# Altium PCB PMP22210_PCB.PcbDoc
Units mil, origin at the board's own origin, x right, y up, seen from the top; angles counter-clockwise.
Board outline 1350 x 1350 mil, 2 copper layers (Top Layer, Bottom Layer), stack 62 mil thick; 26 components, 12 nets, 50 pads, 14 vias.
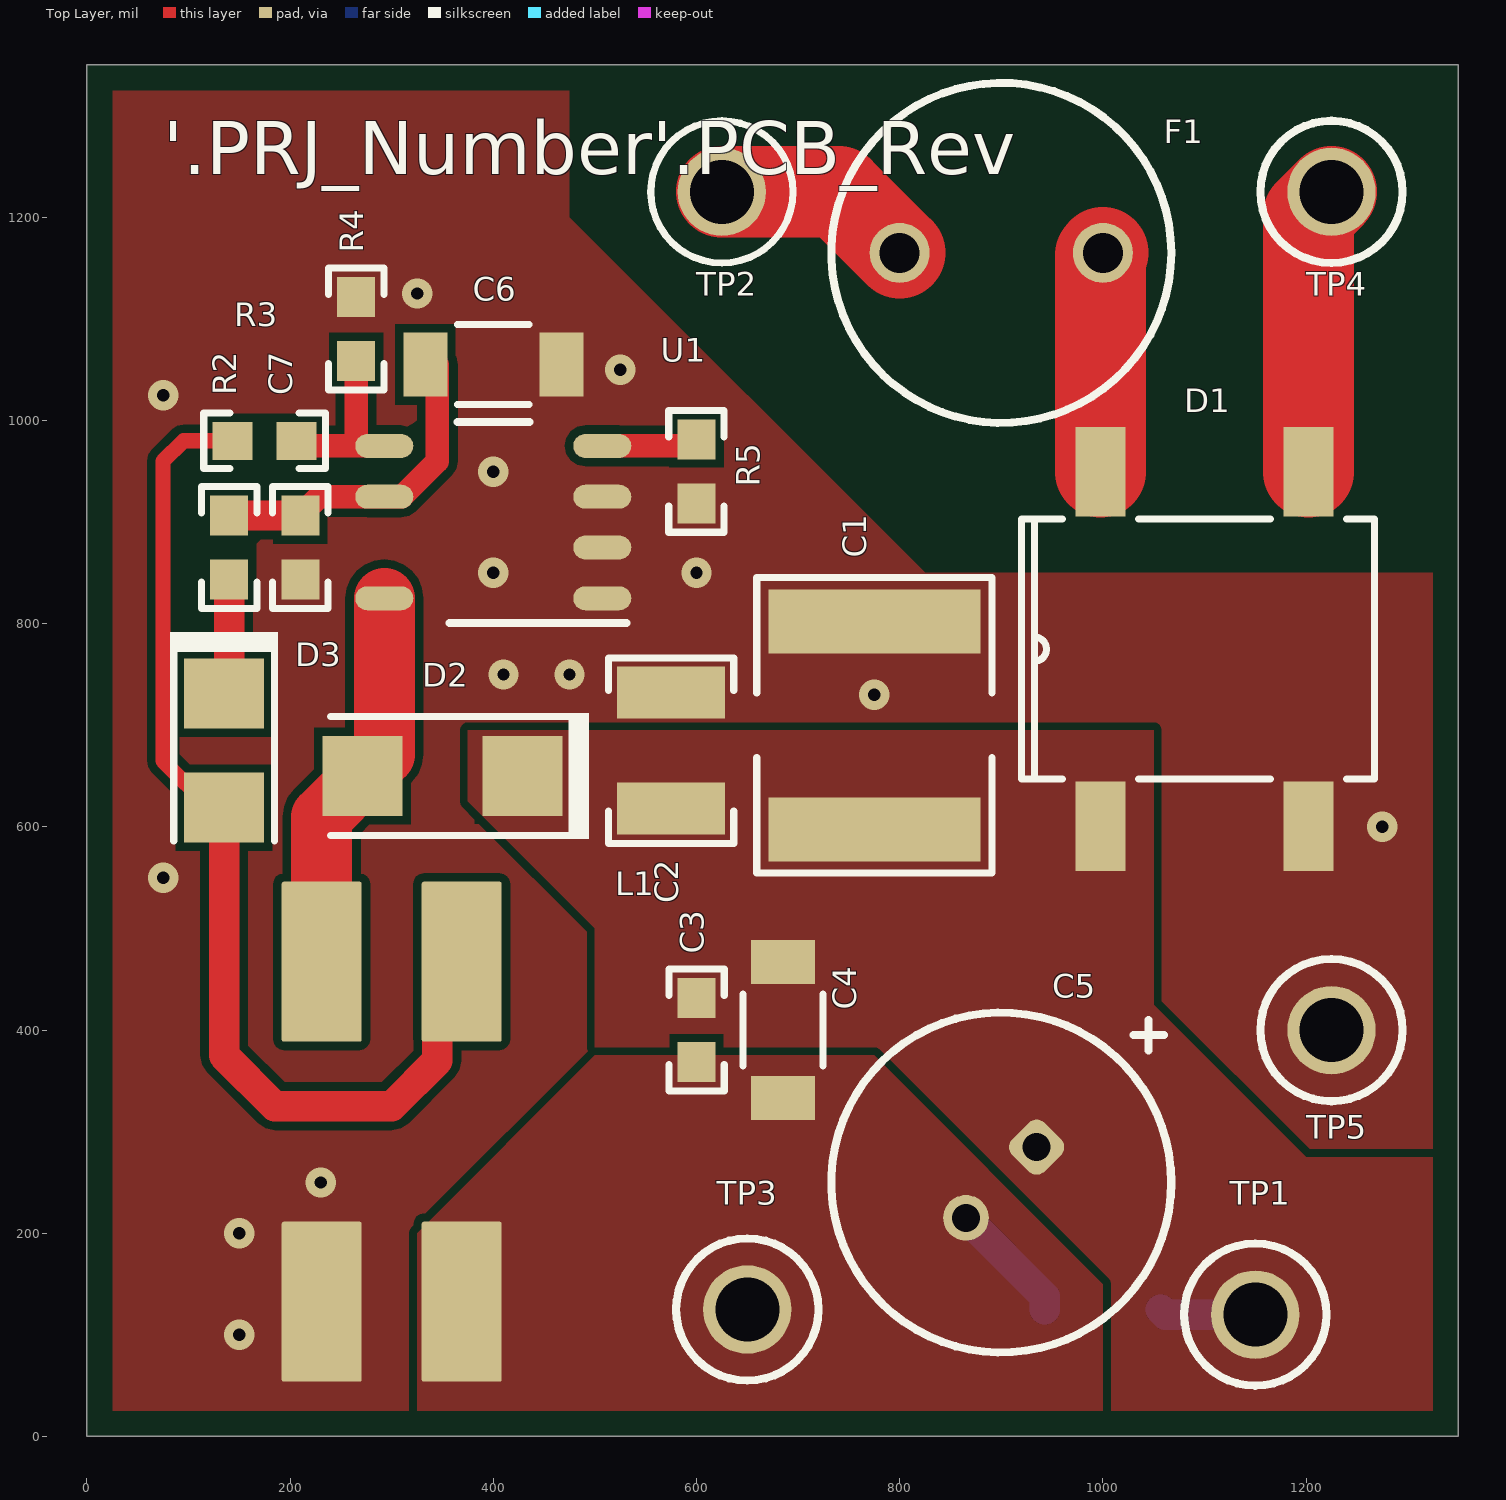
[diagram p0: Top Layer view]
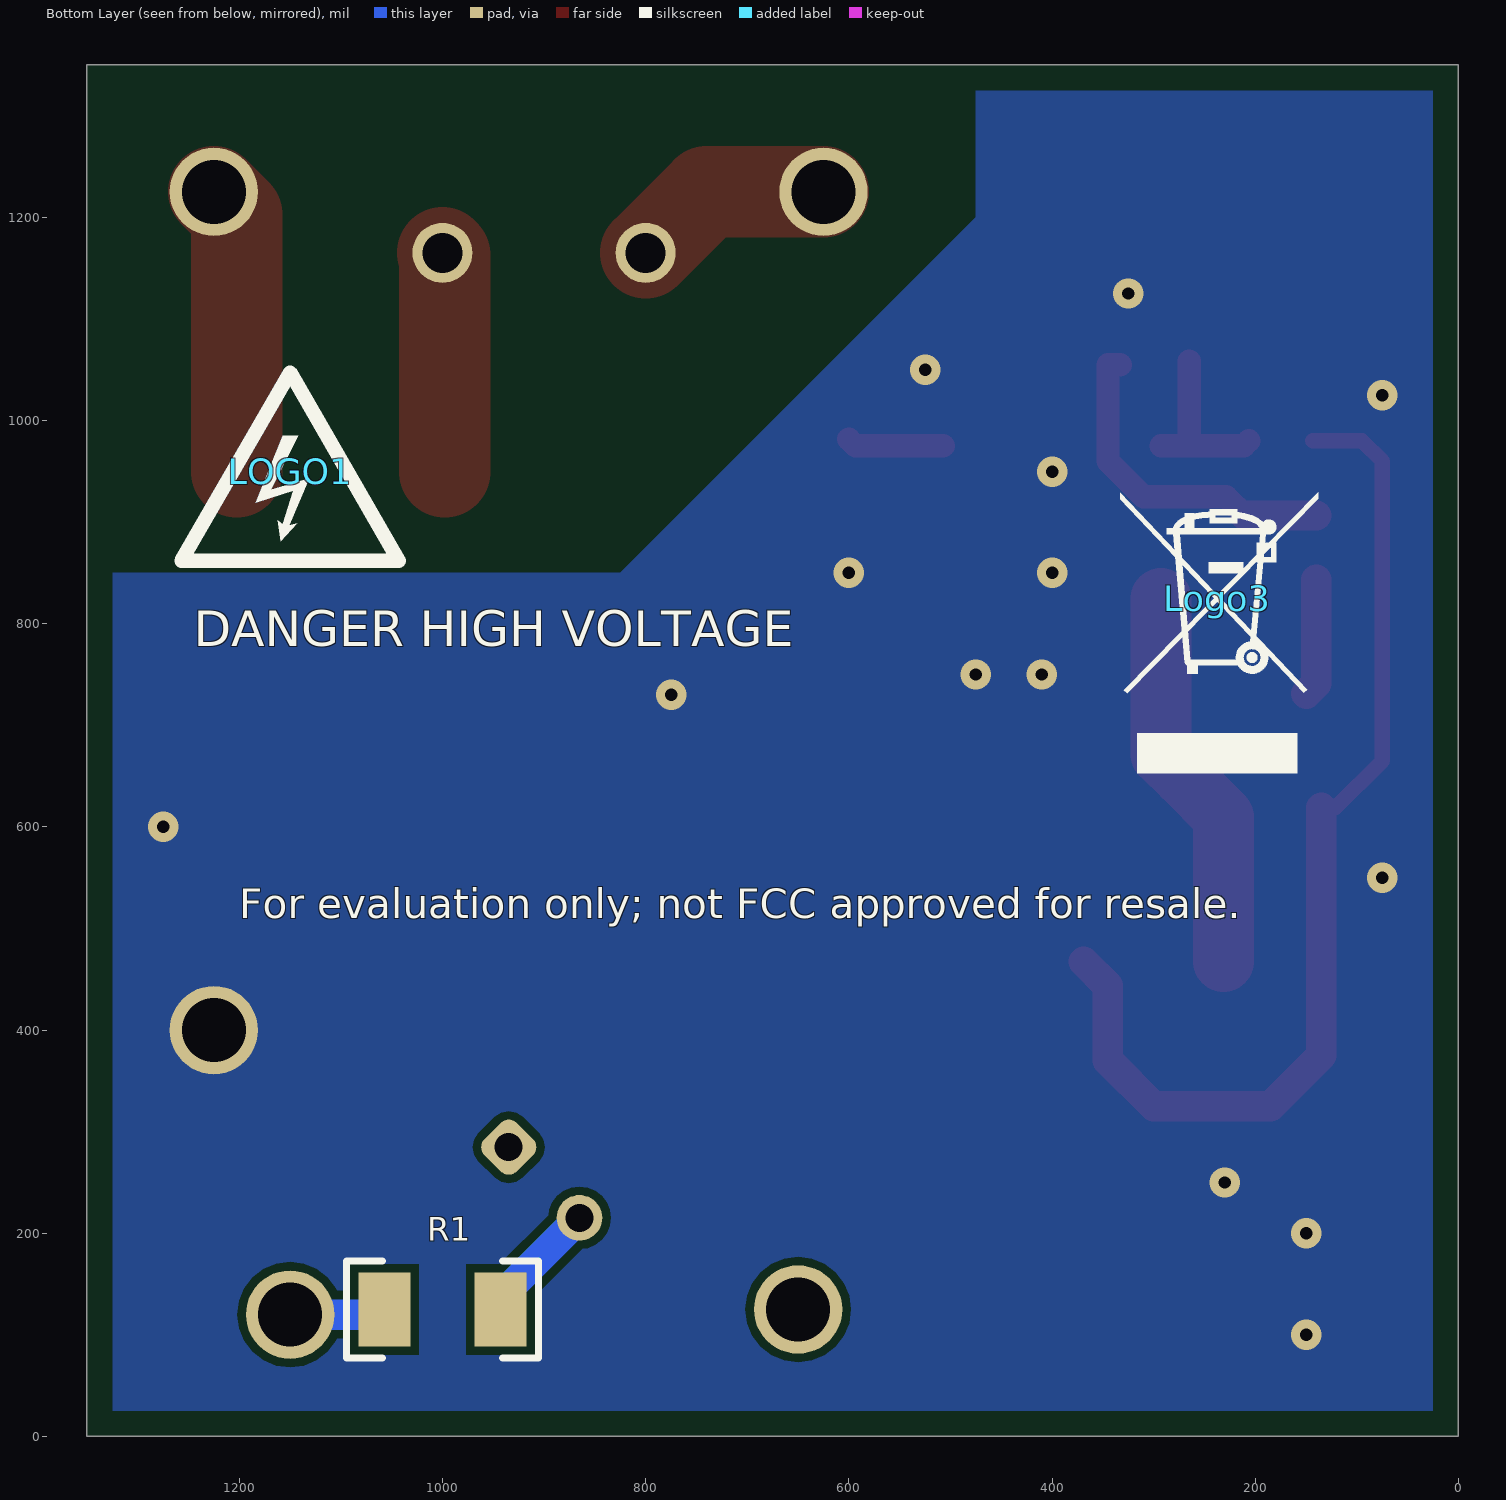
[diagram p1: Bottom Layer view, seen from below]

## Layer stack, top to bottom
Top Solder: solder mask 0.4, Solder Resist, Dk 3.5
Top Layer: signal copper 1.4
Dielectric1: core 59.2, FR-4, Dk 4.8
Bottom Layer: signal copper 1.4
Bottom Solder: solder mask 0.4, Solder Resist, Dk 3.5

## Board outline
0,0 1350,0 1350,1350 0,1350

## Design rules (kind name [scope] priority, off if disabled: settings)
AcuteAngle [All] p1: minimum=4.50000000000000E+0001 checktracksonly=FALSE
AssemblyTestPointUsage [All] p1: valid=2
BoardOutlineClearance BoardOutlineClearance_MountingHoles [OnCopper and InComponentClass('Mounting Holes')] p1: gap=25 ignorepadtopadclearanceinfootprint=FALSE
BoardOutlineClearance BoardOutlineClearance_Poly [OnCopper and InPoly] p2: gap=25 ignorepadtopadclearanceinfootprint=FALSE
BoardOutlineClearance [OnCopper and Not InComponentClass('Logo') and not InComponentClass('FiducialMark') and not InRegion(1000,500,4000,800)] p3: gap=25 ignorepadtopadclearanceinfootprint=FALSE
Clearance Clearance_Keepouts [((IsTrack Or IsArc) And Not InPoly) And IsFree and IsKeepOut vs ((IsTrack Or IsArc) And Not InPoly) And IsFree and IsKeepOut] p1: gap=0 ignorepadtopadclearanceinfootprint=FALSE
Clearance Clearance_Poly [InPolygon] p2: gap=8 ignorepadtopadclearanceinfootprint=FALSE except(0: Arc-Hole Track-Hole SMDPad-Hole THPad-Hole Via-Hole Fill-Hole Poly-Hole Region-Hole Text-Hole)
Clearance [All] p3: gap=7.87 ignorepadtopadclearanceinfootprint=FALSE except(0: Arc-Hole Track-Hole SMDPad-Hole THPad-Hole Via-Hole Fill-Hole Poly-Hole Region-Hole Text-Hole)
ComponentClearance ComponentClearance_MountingHoles_FiducialMarks [InComponentClass('Mounting Holes') vs InComponentClass('FiducialMark')] p1: gap=50 collisioncheckmode=3 verticalgap=10 showdistances=FALSE
ComponentClearance ComponentClearance_Shunt [InComponentClass('Header') vs InComponentClass('Shunt')] p2: gap=0 collisioncheckmode=3 verticalgap=0 showdistances=FALSE
ComponentClearance ComponentClearance_Logo [InComponentClass('Logo')] p3: gap=50 collisioncheckmode=3 verticalgap=10 showdistances=FALSE
ComponentClearance ComponentClearance_ScrewToNut [(HasFootprint('NY PMS 440 0025 PH')) vs (HasFootprint('Keystone_1902C'))] p4: gap=5 collisioncheckmode=3 verticalgap=10 showdistances=FALSE
ComponentClearance ComponentClearance_MountingHoles [InComponentClass('Mounting Holes')] p5: gap=250 collisioncheckmode=3 verticalgap=100000 showdistances=FALSE
ComponentClearance ComponentClearance_SmallPassives [HasFootprint('0201*') or HasFootprint('0402*') or HasFootprint('0508') or HasFootprint('0603*') or HasFootprint('0612') or HasFootprint('0805*') or HasFootprint('0815*') or HasFootprint('0830*') or HasFootprint('1206*') or HasFootprint('1210*') or HasFootprint('1808*') or HasFootprint('1812*') or HasFootprint('1825*') or HasFootprint('2010*') or HasFootprint('2220*') or HasFootprint('2225*') or HasFootprint('2512*') or HasFootprint('2728*') or HasFootprint('3518*') vs HasFootprint('0201*') or HasFootprint('0402*') or HasFootprint('0508') or HasFootprint('0603*') or HasFootprint('0612') or HasFootprint('0805*') or HasFootprint('0815*') or HasFootprint('0830*') or HasFootprint('1206*') or HasFootprint('1210*') or HasFootprint('1808*') or HasFootprint('1812*') or HasFootprint('1825*') or HasFootprint('2010*') or HasFootprint('2220*') or HasFootprint('2225*') or HasFootprint('2512*') or HasFootprint('2728*') or HasFootprint('3518*')] p6: gap=14.96 collisioncheckmode=3 verticalgap=10 showdistances=FALSE
ComponentClearance ComponentClearance_THtoSMT [IsThruComponent vs IsSMTComponent] p7: gap=15 collisioncheckmode=3 verticalgap=30 showdistances=FALSE
ComponentClearance ComponentClearance_THtoTH [IsThruComponent vs IsThruComponent] p8: gap=15 collisioncheckmode=3 verticalgap=30 showdistances=FALSE
ComponentClearance [All] p9: gap=15 collisioncheckmode=3 verticalgap=10 showdistances=FALSE
DiffPairsRouting [All] p1: maxlimit=100 minlimit=10 mostfreqgap=10 toplayer_minwidth=15 toplayer_maxwidth=15 toplayer_prefwidth=15 bottomlayer_minwidth=15 bottomlayer_maxwidth=15 bottomlayer_prefwidth=15 maxuncoupledlength=1000
FabricationTestPointUsage TestPointUsage [All] p1: valid=2 allowmultiple=FALSE
FabricationTestpoint Testpoint [All] p1: side=3 testpointundercomponent=TRUE minsize=40 maxsize=100 preferedsize=60 minholesize=0 maxholesize=40 preferedholesize=32 testpointgrid=1 allowsidetop=TRUE allowsidebottom=TRUE usegrid=TRUE gridtolerance=0.01
FanoutControl Fanout_LCC [IsLCC] p1: bgadir=Out bgaviamode=Centered fanoutstyle=Auto fanoutdirection=Alternating viagrid=1 // Fanout_LCC (Default Rule)
FanoutControl Fanout_BGA [IsBGA] p2: bgadir=Out bgaviamode=Centered fanoutstyle=Auto fanoutdirection=Alternating viagrid=1 // Fanout_BGA (Default Rule)
FanoutControl Fanout_Default [All] p4: bgadir=Out bgaviamode=Centered fanoutstyle=Auto fanoutdirection=Alternating viagrid=1 // Fanout_Default (Default Rule)
FanoutControl Fanout_Small [(CompPinCount < 5)] p5: bgadir=Out bgaviamode=Centered fanoutstyle=Auto fanoutdirection=OutThenIn viagrid=1 // Fanout_Small (Default Rule)
HoleSize [All] p1: absolutevalues=TRUE maxlimit=251 minlimit=7.87 maxpercent=80.000 minpercent=20.000
MinimumAnnularRing MinimumAnnularRing_ThermalPadVias [IsVia and InAnyComponent] p1: minimumring=5.91
MinimumAnnularRing [All] p2: minimumring=8
MinimumSolderMaskSliver MinimumSolderMaskSliver_Logo [InComponentClass('Logo') vs InComponentClass('Logo')] p1: minsoldermaskwidth=0.7
MinimumSolderMaskSliver [All] p2: minsoldermaskwidth=3.94
PlaneConnect [All] p1: planeconnectstyle=Direct reliefexpansion=10 reliefentries=4 reliefconductorwidth=10 reliefairgap=10
PolygonConnect [All] p1: connectstyle=Direct reliefconductorwidth=10 reliefentries=4 polygonreliefangle="90 Angle" airgapwidth=10
RoutingVias ThermalPadVias [IsVia and InAnyComponent] p1: holewidth=7.87 width=19.68 viastyle="Through Hole" minholewidth=7.87 minwidth=19.68 maxholewidth=12.99 maxwidth=23.62
RoutingVias [All] p2: holewidth=16 width=34 viastyle="Through Hole" minholewidth=7.87 minwidth=26 maxholewidth=40 maxwidth=65
SilkToBoardRegionClearance [Not ((IsComment or IsDesignator) And (Hide <> 'False')) and not InRegion(1000,500,4000,800)] p1:
SilkToSilkClearance SilkToSilkClearance_Pb-FreeLogo [(HasFootprint('Pb-Free_Overlay_Medium') OR HasFootprint('Pb-Free_Overlay_Small')) vs (HasFootprint('Pb-Free_Overlay_Medium') OR HasFootprint('Pb-Free_Overlay_Small'))] p1: silktosilkclearance=0
SilkToSilkClearance [All] p2: silktosilkclearance=4
SilkToSolderMaskClearance SilkToComponentPadClearance [IsPad and InAnycomponent] p1: minsilkscreentomaskgap=5 clearancetoexposedcopper=TRUE
SilkToSolderMaskClearance "Silk to Solder Mask Opening" [All] p2: minsilkscreentomaskgap=4 clearancetoexposedcopper=FALSE
SolderMaskExpansion [All] p1: expansion=1.97
Width [All] p1: maxlimit=100 minlimit=6 preferedwidth=10 checkconnectedcopper=TRUE
15 further rules are at their usual default settings.

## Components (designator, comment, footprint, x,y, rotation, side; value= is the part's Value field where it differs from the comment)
C1 "C5750X6S2W225K250KA" 2220_280 775,700 r90 top value=2.2uF
C2 "C1210X104KCRACTU" 1210_250 575,675 r90 top value=0.1uF
C3 "GRM188R71E105KA12D" 0603 600,400 r270 top value=1uF
C4 "C1206C106K3RACTU" 1206_190 685,400 r270 top value=10uF
C5 "UMA1E101MDD1TP" UMA_800x500 900,250 r225 top value=100uF
C6 "C1206C106K3RACTU" 1206_190 400,1055 r0 top value=10uF
C7 "GRM188R71H224KAC4D" 0603 210,875 r270 top value=0.22uF
D1 "DF1504S-T" DF-S 1100,775 r90 top value=400V
D2 "US1J-13-F" SMA 350,650 r180 top value=600V
D3 "CD1408-FU1600" Diode_1408 135,675 r270 top value=600V
F1 "37202500001" FUSE_372 900,1165 r180 top
L1 "MSD1260-105KLB" MSD1260 300,300 r90 top value=1mH
LOGO1 "DANGER HIGH VOLTAGE" IEC_HighVoltage_Small 1150,950 r180 bottom
Logo2 "FCC disclaimer" FCC_disclaimer 5715,6125 r0 top
Logo3 "WEEE logo" WEEE_Minimum 237.27,825 r180 bottom
R1 "CRCW120624K0JNEA" 1206 1000,125 r0 bottom value=24k
R2 "CRCW060310R0JNEA" 0603 140,875 r270 top value=10
R3 "CRCW0603649KFKEA" 0603 175,980 r180 top value=649k
R4 "CRCW0603332KFKEA" 0603 265,1090 r270 top value=332k
R5 "CRCW06038K25FKEA" 0603 600,950 r90 top value=8.25k
TP1 "5010" Keystone5010 1150,120 r0 top
TP2 "5125" Keystone5125 625,1225 r0 top
TP3 "5011" Keystone5011 650,125 r0 top
TP4 "5127" Keystone5127 1225,1225 r0 top
TP5 "5012" Keystone5012 1225,400 r0 top
U1 "UCC28910DR" D0007A_N 400,900 r180 top

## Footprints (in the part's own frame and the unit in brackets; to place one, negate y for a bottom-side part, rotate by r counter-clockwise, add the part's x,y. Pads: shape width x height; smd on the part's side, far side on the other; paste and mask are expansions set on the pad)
0603 [mm] "0603 from SM-752 data"
  rect 1x0.95 smd: 1(-0.8,0) 2(0.8,0)
  silkscreen extent -1.52,-0.69 1.52,0.69, body extent -0.87,-0.47 0.87,0.47, height 1
1206 [mm] "1206 from SM-752 data"
  rect 1.3x1.85 smd: 1(-1.45,0) 2(1.45,0)
  silkscreen extent -2.4,-1.21 2.4,1.21, body extent -1.7,-0.9 1.7,0.9, height 1.35
1206_190 [mm] "1206_190"
  rect 1.1x1.6 smd: 1(-1.7,0) 2(1.7,0)
  silkscreen extent -0.9,-1 0.9,1, body extent -1.75,-0.95 1.75,0.95, height 1.9
1210_250 [mm] "1210"
  rect 1.3x2.7 smd: 1(-1.45,0) 2(1.45,0)
  silkscreen extent -2.32,-1.57 2.32,1.57, body extent -1.7,-1.35 1.7,1.35, height 2.5
2220_280 [mm] "Chip Capacitor, Body 5.7x5.0mm, IPC Medium Density"
  rect 1.6x5.3 smd: 1(-2.6,0) 2(2.6,0)
  silkscreen extent -3.69,-2.94 3.69,2.94, body extent -2.95,-2.62 2.95,2.62, height 2.8
D0007A_N [mm] "SOIC, 7-Leads, Body 4.9x3.9mm, Pitch 1.27mm, IPC Medium Density"
  oval 1.45x0.6 smd: 1(-2.725,1.905) 2(-2.725,0.635) 3(-2.725,-0.635) 4(-2.725,-1.905) 5(2.725,-1.905) 6(2.725,-0.635) 8(2.725,1.905)
  silkscreen extent -3.32,-2.5 1.1,2.52, body extent -3.01,-2.45 3.01,2.45, height 1.75
DF-S [mil] "Diodes Inc. recommended land pattern per ap02001.pdf rev 30"
  rect 88x49 smd: 1(-174.5,102.36) 2(-174.5,-102.36) 3(174.5,-102.36) 4(174.5,102.36)
  silkscreen extent -128,-168 128,180, body extent -205,-168 205,168, height 108
Diode_1408 [mm] "On Semi recommended land pattern for SOD-123"
  rect 1.75x2 smd: 1(-1.425,0) 2(1.425,0)
  silkscreen extent -2.97,-1.35 2.26,1.35, body extent -1.8,-1.05 1.8,1.05, height 1.35
FCC_disclaimer [mil]
FUSE_372 [mm] "LITTELFUSE"
  round 1.5 hole 1: 1(-2.54,0) 2(2.54,0)
  silkscreen extent -4.25,-4.25 4.25,4.25, body extent -4.25,-4.25 4.25,4.25, height 8
IEC_HighVoltage_Small [mil]
  silkscreen extent -107,-88 107,97
Keystone5010 [mil] "Keystone Multipurpose loops"
  round 87 hole 63: 1(0,0)
  silkscreen extent -70,-70 70,70, body extent -63,-63 63,62, height 319
Keystone5011 [mil] "Keystone Multipurpose loops"
  round 87 hole 63: 1(0,0)
  silkscreen extent -70,-70 70,70, body extent -63,-63 63,62, height 319
Keystone5012 [mil] "Keystone Multipurpose loops"
  round 87 hole 63: 1(0,0)
  silkscreen extent -70,-70 70,70, body extent -63,-63 63,62, height 319
Keystone5125 [mil] "Keystone Multipurpose loops"
  round 87 hole 63: 1(0,0)
  silkscreen extent -70,-70 70,70, body extent -63,-63 63,62, height 319
Keystone5127 [mil] "Keystone Multipurpose loops"
  round 87 hole 63: 1(0,0)
  silkscreen extent -70,-70 70,70, body extent -63,-63 63,62, height 319
MSD1260 [mm] "COILCRAFT"
  rrect5% 4x2 smd mask+0.051: 1(-4.25,1.75) 2(-4.25,-1.75) 3(4.25,-1.75) 4(4.25,1.75)
  body extent -6.1,-6.1 6.1,6.1, height 6
SMA [mm] "Molded Diode, 2-Leads, Body 4.3x2.6mm, IPC Medium Density, based on OnSemi component dimensions and land pattern"
  rect 2x2 smd: 1(-2,0) 2(2,0)
  silkscreen extent -3.66,-1.57 2.79,1.57, body extent -2.6,-1.3 2.6,1.3, height 2.42
UMA_800x500 [mil] "TH, 2-Leads, Dia 8mm, Pin Spacing 2.5mm"
  rrect50% 45x45 hole 27.56: 1(-49.21,0)
  round 45 hole 27.56: 2(49.21,0)
  body extent -167,-168 167,168, height 236
WEEE_Minimum [mil] "WEEElie bin"
  silkscreen extent -95,-172 99,104

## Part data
C1: library part CMP-0009372-2, "CAP, CERM, 2.2 uF, 450 V, +/- 10%, X6S, 2220", Cap_Case=2220, Manufacturer=TDK, Supplier Part Number 1=445-7781-1-ND, TempCo=X6S, Tolerance_%=10%, Value1=Unknown, Value2=450V, ValueDisplayed=2.2uF
C2: library part CMP-0009095-1, "CAP, CERM, 0.1 uF, 500 V, +/- 10%, X7R,", Cap_Case=1210, Manufacturer=Kemet, Supplier Part Number 1=399-6769-1-ND, TempCo=X7R, Tolerance_%=10%, Value1=Unknown, Value2=500V, ValueDisplayed=0.1uF
C3: library part CMP-0007405-4, "CAP, CERM, 1 uF, 25 V, +/- 10%, X7R, 0603", Cap_Case=0603, Manufacturer=MuRata, Supplier Part Number 1=490-5307-1-ND, TempCo=X7R, Tolerance_%=10%, Value1=Unknown, Value2=25V, ValueDisplayed=1uF
C4 C6: library part CMP-0008589-2, "CAP, CERM, 10 uF, 25 V, +/- 10%, X7R, 1206_190", Cap_Case=1206, Manufacturer=Kemet, Supplier Part Number 1=399-7442-1-ND, TempCo=X7R, Tolerance_%=10%, Value1=Unknown, Value2=25V, ValueDisplayed=10uF
C5: library part CMP-0084159-1, "CAP, AL, 100 µF, 25 V, +/- 20%, TH", Cap_Case=8x5mm, Manufacturer=Nichicon, Tolerance_%=20%, Value2=25V, ValueDisplayed=100µF
C7: library part CMP-0007445-4, "CAP, CERM, 0.22 uF, 50 V, +/- 10%, X7R, 0603", Cap_Case=0603, Manufacturer=MuRata, Supplier Part Number 1=490-12546-1-ND, TempCo=X7R, Tolerance_%=10%, Value1=Unknown, Value2=50V, ValueDisplayed=0.22uF
D1: library part CMP-0029208-3, "Diode, Switching-Bridge, 400 V, 1.5 A, DF-S", Manufacturer="Diodes Inc.", Value1=1.5A, Value2=1.1V
D2: library part CMP-0077027-2, "Diode, Ultrafast, 600 V, 1 A, SMA", Manufacturer="Diodes Inc.", Value1=1A, Value2=1.7V
D3: library part CMP-0029015-2, "Diode, Ultrafast, 600 V, 1 A, 1408 Diode", Manufacturer=Bourns, Value1=1A, Value2=1.25V
F1: library part CMP-0003546-2, "Fuse, 0.25 A, 250VAC/VDC, TH", Irating_A=250mA, Manufacturer=Littelfuse, Supplier Part Number 1=F5480CT-ND
L1: library part CMP-0012927-3, "Coupled inductor, 1 mH, 0.34 A, 3.06 ohm, SMD", Manufacturer=Coilcraft, ValueDisplayed=1mH
LOGO1: library part CMP-0074835-1, "IEC 61010-1 High Voltage Warning"
Logo2: library part CMP-0074847-1, "FCC_disclaimer"
Logo3: library part CMP-0074769-1
R1: library part CMP-0018634-3, "RES, 24 k, 5%, 0.25 W, AEC-Q200 Grade 0, 1206", Manufacturer=Vishay-Dale, Power_W=250mW, Supplier Part Number 1=541-24KECT-ND, TempCo="200 ppm/C", Tolerance_%=5%, Value2=0.25W, Value_Code=24k0, ValueDisplayed=24k
R2: library part CMP-0025703-4, "RES, 10, 5%, 0.1 W, AEC-Q200 Grade 0, 0603", Manufacturer=Vishay-Dale, Power_W=100mW, Supplier Part Number 1=541-10GCT-ND, TempCo="200 ppm/C", Tolerance_%=5%, Value2=0.1W, Value_Code=10R0, ValueDisplayed=10
R3: library part CMP-0022542-4, "RES, 649 k, 1%, 0.1 W, AEC-Q200 Grade 0, 0603", Manufacturer=Vishay-Dale, Power_W=100mW, Supplier Part Number 1=541-649KHCT-ND, TempCo="100 ppm/C", Tolerance_%=1%, Value2=0.1W, Value_Code=649k
R4: library part CMP-0022336-4, "RES, 332 k, 1%, 0.1 W, AEC-Q200 Grade 0, 0603", Manufacturer=Vishay-Dale, Power_W=100mW, Supplier Part Number 1=541-332KHCT-ND, TempCo="100 ppm/C", Tolerance_%=1%, Value2=0.1W, Value_Code=332k
R5: library part CMP-0022635-4, "RES, 8.25 k, 1%, 0.1 W, AEC-Q200 Grade 0, 0603", Manufacturer=Vishay-Dale, Power_W=100mW, Supplier Part Number 1=541-8.25KHCT-ND, TempCo="100 ppm/C", Tolerance_%=1%, Value2=0.1W, Value_Code=8k25, ValueDisplayed=8.25k
TP1: library part CMP-0055147-1, "Test Point, Multipurpose, Red, TH", Color=Red, Manufacturer=Keystone, Supplier Part Number 1=36-5010-ND
TP2: library part CMP-0055157-1, "Test Point, Multipurpose, Brown, TH", Color=Brown, Manufacturer=Keystone, Supplier Part Number 1=36-5125-ND
TP3: library part CMP-0055148-1, "Test Point, Multipurpose, Black, TH", Color=Black, Manufacturer=Keystone, Supplier Part Number 1=36-5011-ND
TP4: library part CMP-0055156-1, "Test Point, Multipurpose, Blue, TH", Color=Blue, Manufacturer=Keystone, Supplier Part Number 1=36-5127-ND
TP5: library part CMP-0055149-1, "Test Point, Multipurpose, White, TH", Color=White, Manufacturer=Keystone, Supplier Part Number 1=36-5012-ND
U1: library part CMP-0067241-2, "700V Flyback Switcher with Constant-Voltage Constant-Current and Primary-side Control, D0007A (SOIC-7)", Alternate Manufacturer="Texas Instruments", Alternate PartNumber=UCC28910D

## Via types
v1: diameter 29.92, hole 12.2, Top Layer to Bottom Layer, 14 vias

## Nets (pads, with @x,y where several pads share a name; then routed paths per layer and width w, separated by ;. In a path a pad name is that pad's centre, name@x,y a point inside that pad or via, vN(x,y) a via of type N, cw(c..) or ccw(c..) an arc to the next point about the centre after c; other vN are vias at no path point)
GND: C1.2 C2.2 C6.2 C7.2 D1.2 L1.1 R4.1 R5.1 TP5.1 U1.1 U1.2 U1.3
  other v1: 150,100 150,200 230,250 75,550 1275,600 775,730 410,750 475,750 400,850 600,850 400,949.5 75,1025 525,1050 325,1125
NetC1_1: C1.1 C2.1 C3.1 C4.1 C5.1 D1.1 D2.1 R1.2 TP1.1 | length 95
  Bottom Layer w30: R1.2 1062.09,120 TP1.1
NetC3_2: C3.2 C4.2 C5.2 L1.2 R1.1 TP3.1 | length 122.4
  Bottom Layer w30: C5.2 942.91,137.49 R1.1
NetC6_1: C6.1 C7.1 R2.1 U1.6 | length 334.1
  Top Layer w23: C7.1 228.5,925 U1.6 310,925 345,960 345,1055 C6.1
  Top Layer w30: R2.1 C7.1
NetD1_3: D1.3 TP4.1 | length 284.9
  Top Layer w90: D1.3 1202.36,1202.36 TP4.1
NetD1_4: D1.4 F1.1 | length 216.5
  Top Layer w90: D1.4 997.64,1162.64 F1.1
NetD2_2: D2.2 L1.4 U1.8 | length 383.2
  Top Layer w60: L1.4 231.1,609.84 D2.2 292.72,671.46 U1.8
NetD3_1: D3.1 R2.2 | length 116.5
  Top Layer w30: R2.2 140,741.1 D3.1@150,731.1
NetD3_2: D3.2 L1.3 R3.2 | length 1051.4
  Top Layer w15: D3.2 121.1,618.9 75,665 75,960 95,980 R3.2
  Top Layer w30: D3.2 135,375 185,325 300,325 345,370 345,443.43 L1.3
NetF1_2: F1.2 TP2.1 | length 199.9
  Top Layer w90: TP2.1 740,1225 F1.2
NetR3_1: R3.1 R4.2 U1.5 | length 171.8
  Top Layer w23: R3.1 211.5,975 U1.5@265,975 ; R4.2 U1.5@265,975 ; U1.5 U1.5@265,975
NetR5_2: R5.2 U1.4 | length 95.4
  Top Layer w23: U1.4 593.5,975 R5.2

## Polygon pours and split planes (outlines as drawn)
GND on Top Layer "TOP_LAYER_GND_P006" (solid, remove dead copper, pour order 6): 0,0 0,1350 475,1350 475,1200 825,850 1350,850 1350,0
NetC1_1 on Top Layer "TOP_LAYER_NETC1_1_P002" (solid, remove dead copper, pour order 2): 375,695 1050,695 1050,425 1200,275 1350,275 1350,0 500,0 500,500 375,625
NetC3_2 on Top Layer "TOP_LAYER_NETC3_2_P000" (solid, remove dead copper, pour order 0): 325,0 325,200 500,375 775,375 1000,150 1000,0
GND on Bottom Layer "BOTTOM_LAYER_GND_P004" (solid, remove dead copper, pour order 4): 0,0 0,1350 475,1350 475,1200 825,850 1350,850 1350,0

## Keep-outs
Keep-Out Layer:
  text ".Layer_Name" at 577,-858.49 h60

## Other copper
Top Layer:
  text ".Layer_Name" at 577,-858.49 h60
Bottom Layer:
  text ".Layer_Name" at 577,-858.49 h60

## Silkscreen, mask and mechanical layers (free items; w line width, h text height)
Top Overlay:
  circle w8: c900,250 r167.32
  lines w8: 1030,395 1060,395 ; 1045,380 1045,410
  text "'.PRJ_Number'.PCB_Rev" at 75,1225 h90
  text ".Layer_Name" at 577,-858.49 h60
Bottom Overlay:
  text ".Layer_Name" at 577,-858.49 h60
Top Paste:
  text ".Layer_Name" at 577,-858.49 h60
Bottom Paste:
  text ".Layer_Name" at 577,-858.49 h60
Top Solder:
  text ".Layer_Name" at 577,-858.49 h60
  text ".Layer_Name" at 577,-858.49 h60
Bottom Solder:
  text ".Layer_Name" at 577,-858.49 h60
Drill Guide:
  text ".Layer_Name" at 577,-858.49 h60
M1 Board Outline:
  the board outline again, w10
  text ".Layer_Name" at 577,-858.49 h60
M2 Board Dimensions:
  rectangle: 0,-275 125,-150
  rectangle: 125,-400 500,-275
  lines w7: 0,-275 1000,-275 ; 125,-400 125,-150 ; 250,-400 250,-150 ; 500,-400 500,-150 ; 750,-400 750,-150 ; 0,-400 1000,-400 1000,-150 0,-150 0,-400
  text ".Layer_Name" at 577,-858.49 h60
M3 3D STEP Top:
  text ".Layer_Name" at 577,-858.49 h60
M4 3D STEP Bottom:
  text ".Layer_Name" at 577,-858.49 h60
M5 Assembly Top:
  lines w10: -292,-930.17 6308,-930.17 ; -292,-726.83 6310,-726.83 ; -292,-523.5 -292,-1133.5 3713,-1133.5 6310,-1133.5 6310,-523.5 -291.5,-523.5 -291.5,-1133.5 1284,-1133.5 ; 2173,-1133.5 2173,-523.5 ; 3440,-726.83 3440,-523.5 ; 4280,-726.83 4280,-523.5 ; 4902,-1140 4902,-937.17
  text "COMPONENTS MARKED 'DNP' SHOULD NOT BE POPULATED." at 1153.5,-318.5 h60
  text "ASSEMBLY VARIANT:" at 1153,-434 h60
  text ".VariantName" at 2189,-434 h60
  text "PCB VIEWED FROM TOP SIDE" at -228.5,-655.67 h60
  text "BOARD #:" at 2248,-655.67 h60
  text ".PRJ_Number" at 2793.5,-655.67 h60
  text "REV:" at 3638,-655.67 h60
  text ".PCB_Rev" at 3929.5,-655.67 h60
  text "SVN REV:" at 4476,-655.67 h60
  text ".VersionControl_RevNumber" at 4982,-655.67 h60
  text "TID #:" at 2248,-859 h60
  text ".TID" at 2793.5,-859 h60
  text "PLOT NAME =" at -228.5,-1064.34 h60
  text ".plot_File_Name" at 577,-1064.34 h60
  text "GENERATED    :" at 2250,-1064.34 h60
  text ".Print_Date" at 3119.5,-1064.34 h60
  text ".Print_Time" at 3848.5,-1064.34 h60
  text "TEXAS INSTRUMENTS" at 5113,-1064.34 h60
M6 Assembly Bottom:
  lines w10: -292.5,-727.33 6309.5,-727.33 ; -290.5,-930.67 6309.5,-930.67 ; 1115.5,-1140.5 1115.5,-937.67 ; 1737.5,-727.33 1737.5,-524 ; 2577.5,-727.33 2577.5,-524 ; 3844.5,-1134 3844.5,-524 ; 4733.5,-1134 6309,-1134 6309,-524 -292.5,-524 -292.5,-1134 2304.5,-1134 6309.5,-1134 6309.5,-524
  text "COMPONENTS MARKED 'DNP' SHOULD NOT BE POPULATED." at 6102,-318 h60
  text ".VariantName" at 5058,-434 h60
  text "ASSEMBLY VARIANT:" at 6097,-434 h60
  text ".VersionControl_RevNumber" at 1035.5,-656.17 h60
  text "SVN REV:" at 1541.5,-656.17 h60
  text ".PCB_Rev" at 2088,-656.17 h60
  text "REV:" at 2379.5,-656.17 h60
  text ".PRJ_Number" at 3224,-656.17 h60
  text "BOARD #:" at 3769.5,-656.17 h60
  text "PCB VIEWED FROM BOTTOM SIDE" at 6246,-656.17 h60
  text ".TID" at 3224,-859.5 h60
  text "TID #:" at 3769.5,-859.5 h60
  text "TEXAS INSTRUMENTS" at 904.5,-1064.84 h60
  text ".Print_Time" at 2169,-1064.84 h60
  text ".Print_Date" at 2898,-1064.84 h60
  text "GENERATED    :" at 3767.5,-1064.84 h60
  text ".plot_File_Name" at 5440.5,-1064.84 h60
  text "PLOT NAME =" at 6246,-1064.84 h60
M9 Title Sheet:
  drawing of 57 lines, arcs and shapes, not listed
  text "1" at 739.84,8036.5 h70
  text "2" at 3235.5,8036.5 h70
  text "3" at 5724.84,8036.5 h70
  text "4" at 8231.51,8036.5 h70
  text "5" at 10730.5,8036.5 h70
  text "6" at 13235.5,8036.5 h70
  text "A" at -416.5,6893.5 h70
  text "A" at 14383.5,6893.5 h70
  text "B" at -416.5,4513.5 h70
  text "B" at 14383.5,4513.5 h70
  text "C" at -416.5,2138.5 h70
  text "C" at 14383.5,2138.5 h70
  text "PROJECT TITLE:" at 11343.5,277.5 h45
  text ".PRJ_Title" at 11393.5,144.17 h70
  text "DESIGNED FOR:" at 11343.5,-23.5 h45
  text ".PRJ_Customer" at 11393.5,-163.5 h70
  text "D" at -416.5,-231.5 h70
  text "D" at 14383.5,-231.5 h70
  text "FILE NAME:" at 11343.5,-323.5 h45
  text ".PCB_File_Name_No_Path" at 11393.5,-443.5 h70
  text "Texas Instruments (TI) and/or its licensors do not warrant the accuracy or completeness of this specification" at 6374,-605.34 h45
  text "ENGINEER:" at 11343.5,-613.5 h45
  text "LAYOUT BY:" at 12848.5,-613.5 h45
  text "or any information contained therein. TI and/or its licensors do not warrant that this design will meet" at 6329.01,-718 h45
  text ".PRJ_Engineer" at 11393.5,-768.49 h70
  text ".PCB_Layout" at 12899,-768.49 h70
  text "the specifications, will be suitable for your application or fit for any particular purpose, or will operate in" at 6329.01,-830.67 h45
  text ".Layer_Name" at 577,-858.49 h60
  text "ALTIUM DESIGNER VERSION:" at 12848.5,-923.5 h45
  text "an implementation. TI and/or its licensors do not warrant that the design is production worthy. You should" at 6329.01,-943.33 h45
  text "completely validate and test your design implementation to confirm the system functionality for your application." at 6374,-1056 h45
  text ".print_Scale" at 11393.5,-1056.83 h70
  text ".Application_BuildNumber" at 12899,-1056.83 h70
  text "1" at 739.84,-1263.5 h70
  text "2" at 3235.5,-1263.5 h70
  text "3" at 5724.84,-1263.5 h70
  text "4" at 8231.51,-1263.5 h70
  text "5" at 10730.5,-1263.5 h70
  text "6" at 13235.5,-1263.5 h70
M10 Fab Notes:
  drawing of 189 lines, arcs and shapes, not listed
  text "DESIGN INFORMATION" at 12382.02,6356.17 h60
  text "MIN. TRACK WIDTH:" at 11737.46,6224.05 h60
  text "8" at 12833.7,6224.05 h60
  text "MIL" at 12988.46,6224.05 h60
  text "MIN. CLEARANCE:" at 11737.46,6099.92 h60
  text "0.2" at 12773.7,6099.93 h60
  text "mm" at 12988.46,6099.92 h60
  text "MIN. VIA PAD SIZE:" at 11737.46,5975.8 h60
  text "24" at 12803.71,5975.8 h60
  text "MIL" at 12988.46,5975.8 h60
  text "0.05mm (2MIL)" at 12432.46,5845.9 h60
  text "MINIMUM ANNULAR RING" at 11408.23,5837.67 h60
  text "EXTERNAL" at 13140.46,5837.67 h60
  text "PER" at 11608.23,5727.55 h60
  text "IPC-D-275 CLASS 2 LEVEL C" at 11828.23,5727.54 h60
  text "MIL, HOLES" at 13316.46,5627.07 h60
  text "+/-" at 12924,5618.48 h60
  text "+/-" at 13778,5618.48 h60
  text "REGISTRATION TOLERANCES:" at 11408.23,5617.42 h60
  text "METAL" at 12608,5617.42 h60
  text "5" at 13184.2,5617.42 h60
  text "3" at 14017.2,5617.42 h60
  text "MIL" at 14133.46,5617.42 h60
  text "HOLE SIZE TOLERANCE (UNLESS OTHERWISE SPECIFIED):" at 11408.23,5519.1 h60
  text "+/-" at 13778,5516.23 h60
  text "3" at 14017.2,5515.17 h60
  text "MIL" at 14133.46,5515.17 h60
  text "MATERIAL:" at 11333.46,5377.52 h60
  text "FR-4 High Tg" at 12319.9,5249 h60
  text "X" at 12175.46,5241.01 h60
  text "FR-408" at 11754.46,5236.49 h60
  text "OTHER" at 13242.46,5236.49 h60
  text "62 MIL (1.6mm) +/-10%" at 12074.56,5093.46 h60
  text "X" at 11954.46,5091.01 h60
  text "THICKNESS:" at 11408.23,5085.24 h60
  text "OTHER" at 13359.46,5085.24 h60
  text "TOLERANCE:" at 11408.23,4946.92 h60
  text "X" at 12256.46,4946.92 h60
  text "ANSI IPC-6012 TYPE 3 CLASS 2" at 12434.48,4946.92 h60
  text "OTHER +/-" at 12434.46,4802.73 h60
  text "BOW & TWIST:" at 11408.23,4657.54 h60
  text "X" at 12256.46,4657.54 h60
  text "ANSI IPC-6012 TYPE 3 CLASS 2" at 12434.48,4657.54 h60
  text "OTHER +/-" at 12434.46,4510.85 h60
  text "DRILLING:" at 11333.46,4380.23 h60
  text "NC_DRILL FILES" at 13094.46,4275.04 h60
  text "REFERENCE:" at 11408.23,4271.1 h60
  text "X" at 12065.46,4271.01 h60
  text "AS SHOWN" at 12243.46,4271.1 h60
  text "X" at 12966.46,4271.1 h60
  text "OTHER" at 13392.46,4128.85 h60
  text "PTH COPPER THICKNESS:" at 11407.91,4125.32 h60
  text "X" at 12547.14,4125.32 h60
  text "20-30 um" at 12675.14,4125.32 h60
  text "BOARD FINISH:" at 11333.46,3977.73 h60
  text "SILKSCREEN:" at 11488.68,3867.6 h60
  text "X" at 12446.46,3867.6 h60
  text "TOP" at 12563.46,3867.6 h60
  text "X" at 12956.46,3867.6 h60
  text "BOTTOM" at 13074.46,3867.6 h60
  text "SILKSCREEN COLOR:" at 11488.68,3712.41 h60
  text "X" at 12445.46,3712.41 h60
  text "WHITE" at 12563.46,3712.41 h60
  text "OTHER" at 13074.46,3712.41 h60
  text "X" at 12576.46,3568.96 h60
  text "GREEN" at 12694.46,3568.96 h60
  text "OTHER" at 13312.46,3568.96 h60
  text "SOLDER RESIST COLOR:" at 11488.68,3562.1 h60
  text "X" at 12576.46,3414.71 h60
  text "MATTE" at 12694.46,3414.71 h60
  text "SEMI-GLOSS" at 13312,3414.07 h60
  text "IMMERSION GOLD (ENIG)" at 12394.46,3241.94 h60
  text "ENEPIG" at 13732,3234.72 h60
  text "SURFACE FINISH:" at 11333.46,3233.72 h60
  text "X" at 12216.46,3233.72 h60
  text "IMM. TIN/SILVER OR EQUIV" at 11663,3096.4 h60
  text "OTHER" at 13094.46,3092.47 h60
  text "ARRAY/PANEL:" at 11333.46,2937.09 h60
  text "CUT AND TRIM PER M1 BOARD OUTLINE" at 12394.46,2928.87 h60
  text "N.C. ROUTE" at 12394.46,2792.9 h60
  text "X" at 13082.46,2792.9 h60
  text "V. SCORE" at 13260.46,2792.9 h60
  text "CERTIFICATION:" at 11333.46,2663.77 h60
  text "MATERIALS AND WORKMANSHIP FOR ALL PCBS" at 12058.46,2663.77 h60
  text "TO MEET OR EXCEED THE REQUIREMENTS OF:" at 12058.46,2569.71 h60
  text "X" at 11695.97,2441.08 h60
  text "ANSI IPC-A-600F CLASS ->" at 11823.96,2441.08 h60
  text "X" at 13471.97,2441.08 h60
  text "2" at 13581.96,2441.08 h60
  text "1" at 13266.96,2439.58 h60
  text "3" at 13935.96,2439.58 h60
  text "X" at 12507.97,2293.39 h60
  text "RoHS" at 12635.96,2293.39 h60
  text "OTHER" at 13280.36,2293.39 h60
  text "PER ORDER" at 13677.42,2293.39 h60
  text "ALL BOARDS MUST MEET OR EXCEED UL94-V0 REQUIREMENTS." at 11361,2139.57 h60
  text "PCB MUST BEAR THE UL94V-0 UL REGISTERED MATERIAL ID NUMBER" at 11361,2023.5 h60
  text "ADDITIONAL REQUIREMENTS:" at 11333.46,1854.08 h60
  text "MICROSECTION:" at 11408.23,1746.95 h60
  text "YES" at 12313.96,1746.95 h60
  text "REQUIRED" at 13175.46,1602.62 h60
  text "BARE BOARD ELEC. TEST:" at 11408.23,1599.76 h60
  text "NONE" at 12713.96,1599.76 h60
  text "X" at 13057.46,1599.76 h60
  text "PER ORDER" at 13767.46,1599.76 h60
  text "XX MIL VIAS REQUIRE NON-CONDUCTIVE FILL AND PLANARIZE" at 11576.38,1394.82 h59
  text "XX MIL VIAS REQUIRE CONDUCTIVE FILL AND PLANARIZE" at 11584.38,1290.84 h60
  text "OUTER XX MIL TRACES REQUIRE 50 OHM SINGLE-ENDED IMPEDANCE" at 11583.39,1127.46 h58
  text "LAYER 2 & 3 (INNER LAYERS) XX MIL WIDE, XX MIL SPACE / TRACES REQUIRE 100 OHM DIFFERENTIAL IMPEDANCE" at 11575.39,891.74 h60
  text ".Layer_Name" at 577,-858.49 h60
M11 Gerber Information:
  lines w10: -292,-930.17 6308,-930.17 ; -292,-726.83 6310,-726.83 ; -292,-523.5 -292,-1133.5 3713,-1133.5 6310,-1133.5 6310,-523.5 -291.5,-523.5 -291.5,-1133.5 1284,-1133.5 ; 2173,-1133.5 2173,-523.5 ; 3440,-726.83 3440,-523.5 ; 4280,-726.83 4280,-523.5 ; 4902,-1140 4902,-937.17
  text "ALL ARTWORK VIEWED FROM TOP SIDE" at -228.5,-655.67 h60
  text "BOARD #:" at 2248,-655.67 h60
  text ".PRJ_Number" at 2793.5,-655.67 h60
  text "REV:" at 3638,-655.67 h60
  text ".PCB_Rev" at 3929.5,-655.67 h60
  text "SVN REV:" at 4476,-655.67 h60
  text ".VersionControl_RevNumber" at 4982,-655.67 h60
  text "LAYER NAME =" at -228.5,-858.49 h60
  text "TID #:" at 2248,-859 h60
  text ".TID" at 2793.5,-859 h60
  text "PLOT NAME =" at -228.5,-1064.34 h60
  text ".plot_File_Name" at 577,-1064.34 h60
  text "GENERATED    :" at 2250,-1064.34 h60
  text ".Print_Date" at 3119.5,-1064.34 h60
  text ".Print_Time" at 3848.5,-1064.34 h60
  text "TEXAS INSTRUMENTS" at 5113,-1064.34 h60
M12 Stackup:
  drawing of 191 lines, arcs and shapes, not listed
  text "Layer" at 9797.84,7717.5 h60
  text "Name" at 10207.76,7717.5 h60
  text "Material" at 11137.5,7717.5 h60
  text "Thickness" at 11997.27,7717.5 h60
  text "Constant" at 12647.1,7717.5 h60
  text "Board Layer Stack" at 13216.96,7717.5 h60
  text "1" at 9797.84,7597.5 h60
  text "Top Overlay" at 10207.76,7597.5 h60
  text "2" at 9797.84,7477.5 h60
  text "Top Solder" at 10207.76,7477.5 h60
  text "Solder Resist" at 11137.5,7477.5 h60
  text "0.40mil" at 11997.27,7477.5 h60
  text "3.5" at 12647.1,7477.5 h60
  text "3" at 9797.84,7357.5 h60
  text "Top Layer" at 10207.76,7357.5 h60
  text "Copper" at 11137.5,7357.5 h60
  text "1.40mil" at 11997.27,7357.5 h60
  text "4" at 9797.84,7237.5 h60
  text "Dielectric1" at 10207.76,7237.5 h60
  text "FR-4" at 11137.5,7237.5 h60
  text "59.20mil" at 11997.27,7237.5 h60
  text "4.8" at 12647.1,7237.5 h60
  text "5" at 9797.84,7117.5 h60
  text "Bottom Layer" at 10207.76,7117.5 h60
  text "Copper" at 11137.5,7117.5 h60
  text "1.40mil" at 11997.27,7117.5 h60
  text "6" at 9797.84,6997.5 h60
  text "Bottom Solder" at 10207.76,6997.5 h60
  text "Solder Resist" at 11137.5,6997.5 h60
  text "0.40mil" at 11997.27,6997.5 h60
  text "3.5" at 12647.1,6997.5 h60
  text "7" at 9797.84,6877.5 h60
  text "Bottom Overlay" at 10207.76,6877.5 h60
  text ".Layer_Name" at 577,-858.49 h60
M13 Component Bodies Top:
  text ".Layer_Name" at 577,-858.49 h60
M14 Component Bodies Bottom:
  text ".Layer_Name" at 577,-858.49 h60
M15 Courtyards Top:
  text ".Layer_Name" at 577,-858.49 h60
M16 Courtyards Bottom:
  text ".Layer_Name" at 577,-858.49 h60
Drill Drawing:
  text ".Layer_Name" at 577,-858.49 h60
M17 Embedded Cavity:
  text ".Layer_Name" at 577,-858.49 h60
M18 Embedded Assembly:
  text ".Layer_Name" at 577,-858.49 h60
M19 Embedded Keepout:
  text ".Layer_Name" at 577,-858.49 h60

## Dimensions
0,-400 to 1000,-400 on M2 Board Dimensions
0,0 to 0,1350 on M2 Board Dimensions
0,0 to 1350,0 on M2 Board Dimensions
